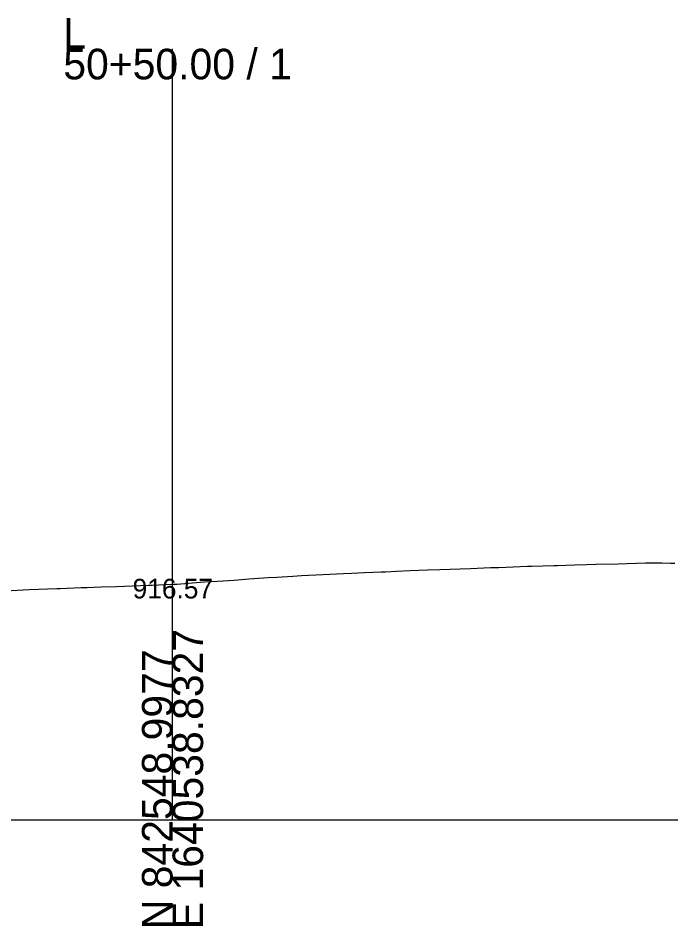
# Model space of a CAD drawing. Extents: x -26 to 1638757, y -10 to 843341.
# Drawn here: x 1135.9 to 1195.6, y 2490.3 to 2573.4 of the extents above; entities that cross this region are included whole.
import ezdxf

# ---------------------------------------------------------------- set-up
doc = ezdxf.new("R2010")
doc.units = 0
for name, color, linetype in [('Exist Cross Section Cell', 7, 'Continuous'), ('Exist XS Center Line Elevation Label', 7, 'Continuous'), ('Exist XS Ground Line', 7, 'Continuous'), ('Scratch_Level_0', 7, 'Continuous')]:
    doc.layers.add(name, color=color, linetype=linetype)

msp = doc.modelspace()

# ---------------------------------------------------------------- linework, layer by layer
at = {"layer": 'Exist Cross Section Cell'}
for p, q in [((1150, 2500), (1150, 2570.582)), ((950, 2500), (1150, 2500)), ((1150, 2500), (1350, 2500))]:
    msp.add_line(p, q, dxfattribs=at)
at = {"layer": 'Exist XS Ground Line'}
msp.add_lwpolyline([(1134.123, 2520.933), (1136.887, 2521.076), (1139.404, 2521.186), (1139.713, 2521.185), (1141.626, 2521.266), (1142.195, 2521.284), (1143.46, 2521.33), (1144.885, 2521.378), (1147.795, 2521.473), (1148.141, 2521.488), (1150, 2521.57), (1150.43, 2521.59), (1152.179, 2521.729), (1152.957, 2521.779), (1154.104, 2521.856), (1155.648, 2521.959), (1156.987, 2522.062), (1158.329, 2522.162), (1158.766, 2522.183), (1159.562, 2522.233), (1161.029, 2522.318), (1161.803, 2522.36), (1163.751, 2522.462), (1165.653, 2522.545), (1166.41, 2522.579), (1167.578, 2522.634), (1169.1, 2522.701), (1169.503, 2522.72), (1170.514, 2522.783), (1171.75, 2522.832), (1173.352, 2522.882), (1174.481, 2522.926), (1177.278, 2523.026), (1179.127, 2523.094), (1179.863, 2523.119), (1182.508, 2523.222), (1182.894, 2523.237), (1184.901, 2523.284), (1185.244, 2523.292), (1186.826, 2523.341), (1187.934, 2523.37), (1188.751, 2523.394), (1190.805, 2523.447), (1193.315, 2523.525), (1194.811, 2523.519), (1195.591, 2523.501), (1196.006, 2523.497)], dxfattribs=at)

# ---------------------------------------------------------------- texts
at = {"layer": 'Exist Cross Section Cell'}
for s, p in [('L', (1140, 2570.582)), ('50+50.00 / 1', (1140, 2567.782))]:
    msp.add_text(s, height=2.8, dxfattribs=at).set_placement(p)
for s, p in [('E 1640538.8327', (1152.8, 2490)), ('N 842548.9977', (1150, 2490))]:
    msp.add_text(s, height=2.8, rotation=90, dxfattribs=at).set_placement(p)
at = {"layer": 'Exist XS Center Line Elevation Label'}
msp.add_text('916.57', height=1.8, dxfattribs=at).set_placement((1146.346, 2520.27))
at = {"layer": 'Scratch_Level_0'}
for s, p in [('Exterior Boundary', (1194.813, 2523.518)), ('LT_Slope_Cut', (1194.827, 2523.518))]:
    msp.add_text(s, height=0.01, dxfattribs=at).set_placement(p)

doc.saveas('drawing.dxf')
